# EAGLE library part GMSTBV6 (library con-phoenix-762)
PHOENIX
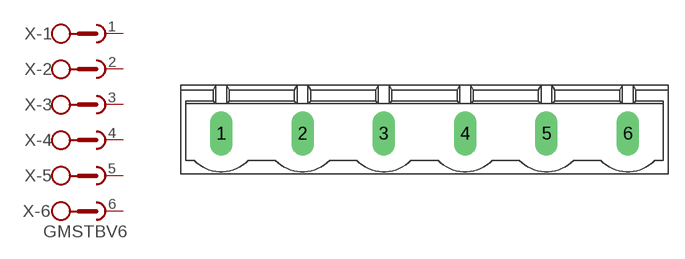
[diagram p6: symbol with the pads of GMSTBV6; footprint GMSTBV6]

Designator prefix X; gates -1=SKB -2=SKB -3=SKB -4=SKB -5=SKB -6=SKBV

## GMSTBV6 (MPN: GMSTBVA2,5/6-G-7,62; OC_FARNELL: 1793084; OC_NEWARK: 69R9524)  [GMSTBV6]
1  -1:1  pas
2  -2:1  pas
3  -3:1  pas
4  -4:1  pas
5  -5:1  pas
6  -6:1  pas

## Footprint GMSTBV6 (pad centres in mm)
PHOENIX
drill 1.397 long: 1 -19.05,0; 2 -11.43,0; 3 -3.81,0; 4 3.81,0; 5 11.43,0; 6 19.05,0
